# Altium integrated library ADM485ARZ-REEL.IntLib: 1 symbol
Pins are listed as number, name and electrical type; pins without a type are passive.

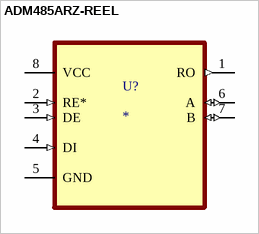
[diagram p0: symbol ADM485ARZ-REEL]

## ADM485ARZ-REEL
designator U?
5 V, Low Power, 5 Mbps, Half Duplex EIA RS-485 Transceiver; MF: Analog Devices; MP: ADM485ARZ
footprint SOIC127P600X175-8N
pins: 1 RO (out), 2 RE* (in), 3 DE (in), 4 DI (in), 5 GND, 6 A (io), 7 B (io), 8 VCC (power)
